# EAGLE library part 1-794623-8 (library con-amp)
MICRO MATE N LOK Dual Row, grid 1.5 mm Source: http://catalog.tycoelectronics.com .. ENG_CD_794623_F.pdf
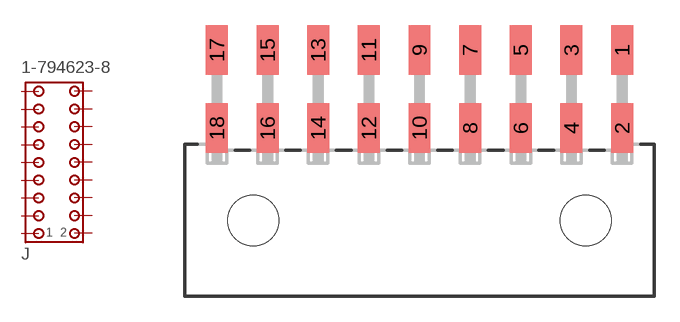
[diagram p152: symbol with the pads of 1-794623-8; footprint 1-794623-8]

Designator prefix J

## 1-794623-8 (MF: TYCO ELECTRONICS; MPN: 1-794623-8; OC_FARNELL: unknown; OC_NEWARK: 10H3686)  [1-794623-8]
1  1  pas
2  2  pas
3  3  pas
4  4  pas
5  5  pas
6  6  pas
7  7  pas
8  8  pas
9  9  pas
10  10  pas
11  11  pas
12  12  pas
13  13  pas
14  14  pas
15  15  pas
16  16  pas
17  17  pas
18  18  pas

## Footprint 1-794623-8 (pad centres in mm)
MICRO MATE N LOK Dual Row, grid 1.5 mm Source: http://catalog.tycoelectronics.com .. ENG_CD_794623_F.pdf
smd 1.3 x 2.92: 1 12,10.1; 2 12,5.48; 3 9,10.1; 4 9,5.48; 5 6,10.1; 6 6,5.48; 7 3,10.1; 8 3,5.48; 9 0,10.1; 10 0,5.48; 11 -3,10.1; 12 -3,5.48; 13 -6,10.1; 14 -6,5.48; 15 -9,10.1; 16 -9,5.48; 17 -12,10.1; 18 -12,5.48
hole 3 at -9.85,0
hole 3 at 9.85,0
